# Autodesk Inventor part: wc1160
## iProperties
Shininess: 64.0
Length Units: 11272
Angle Units: 11279
Time Units: 11290
Mass Units: 11286
Length Display Precision: 3
Angle Display Precision: 2
Compacted: True
Part Number: wc1160
Document SubType Name: Modeling
Created: 2004-08
Designer: John Blackburn
Manufacturer: Standard
Standards Organization: Custom
Material: Phenolic
Density: 0.0
Volumn: 0.0
Area: 0.0
PropertySet Name: Model Information
Control State: 0
Master: False
Checked Out: False
Author: John Blackburn
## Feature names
1. Base1
